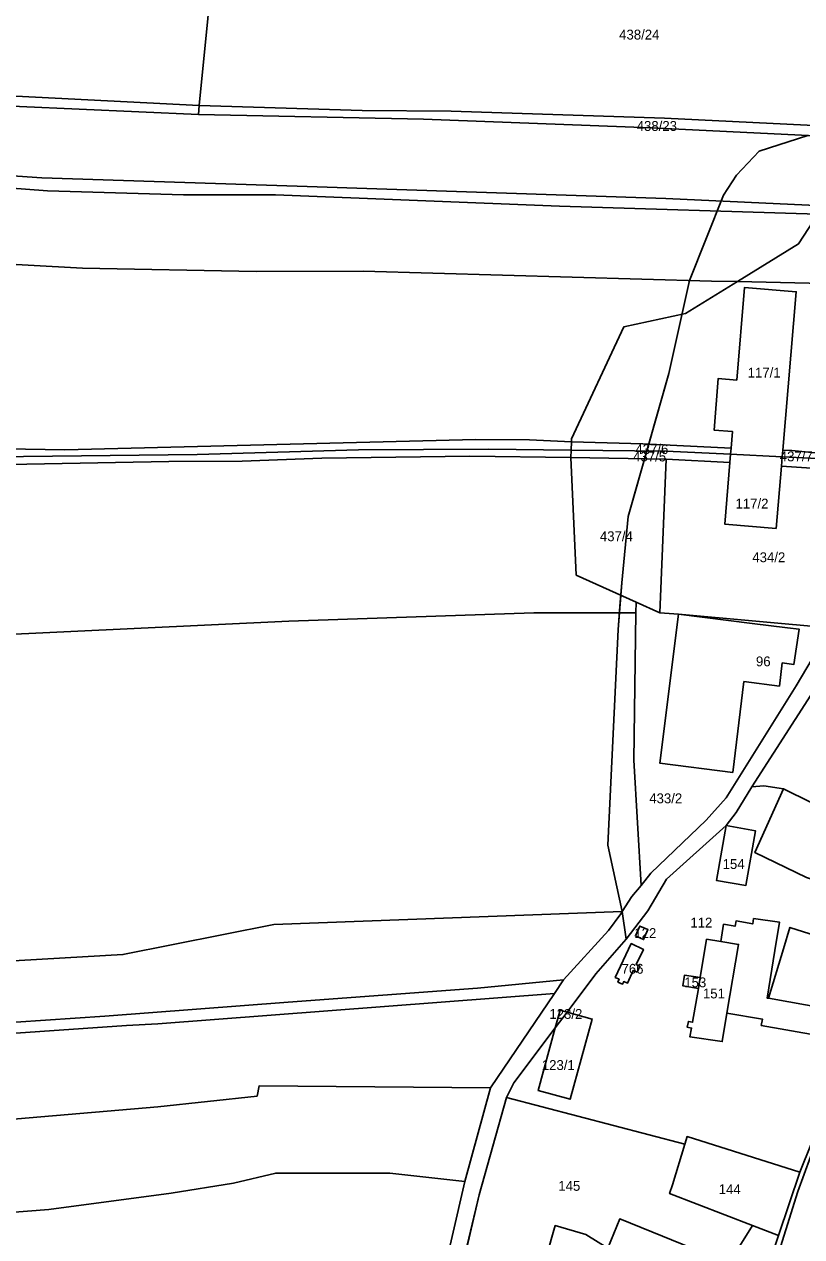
# Model space of a CAD drawing. Extents: x -629983 to -626385, y -1072828 to -1067897.
# Drawn here: x -627910.7 to -627674, y -1070665.2 to -1070295.9 of the extents above; entities that cross this region are included whole.
import ezdxf

# ---------------------------------------------------------------- set-up
doc = ezdxf.new("R2010")
doc.units = 0
for name, color, linetype in [('Parcela nároku', 7, 'Continuous'), ('Parcelní číslo', 7, 'Continuous'), ('Plocha PÚ', 7, 'Continuous'), ('Vnitřní obvod_šetřený', 7, 'Continuous')]:
    doc.layers.add(name, color=color, linetype=linetype)

msp = doc.modelspace()

# ---------------------------------------------------------------- linework, layer by layer
at = {"layer": 'Parcela nároku'}
for points in [[(-628060.11, -1070271.11), (-628056.15, -1070244.07), (-628008.92, -1070250.2), (-627943.87, -1070258.43), (-627852.12, -1070267.55), (-627857.41, -1070320.6), (-627935.31, -1070316.64), (-627972.58, -1070313.71), (-628063.81, -1070300.51)], [(-627694, -1070279.01), (-627762.73, -1070274.69), (-627852.12, -1070267.55), (-627857.41, -1070320.6), (-627807.86, -1070322.13), (-627780.69, -1070322.36), (-627715.75, -1070324.53), (-627668.16, -1070326.84), (-627643.99, -1070328.38), (-627633.37, -1070319.16), (-627623.56, -1070329.68), (-627607.68, -1070330.66), (-627612.15, -1070314.31), (-627620.1, -1070282.88)], [(-627975.41, -1070316.56), (-628013.39, -1070311.63), (-628064.17, -1070304.46), (-628158.28, -1070288.4), (-628169.7, -1070285.94), (-628193.03, -1070281.15), (-628197.85, -1070304.82), (-628163.72, -1070310.89), (-628107.67, -1070319.94), (-627998.49, -1070336.29), (-627905.29, -1070342.7), (-627827.64, -1070345.16), (-627715.35, -1070349), (-627667.5, -1070351.19), (-627663.96, -1070345.7), (-627647.13, -1070331.03), (-627719.77, -1070327.49), (-627789.19, -1070324.83), (-627857.63, -1070323.4), (-627930.45, -1070320.12)], [(-627935.31, -1070316.64), (-627857.41, -1070320.6), (-627857.63, -1070323.4), (-627930.45, -1070320.12), (-627975.41, -1070316.56), (-628013.39, -1070311.63), (-628064.17, -1070304.46), (-628063.81, -1070300.51), (-627972.58, -1070313.71)], [(-627903.57, -1070346.68), (-627931.89, -1070344.45), (-627993.13, -1070340.27), (-628115.46, -1070322.29), (-628198.34, -1070307.23), (-628203.34, -1070331.74), (-628177.12, -1070337.23), (-628130.58, -1070346.23), (-628080.75, -1070353.83), (-628037.7, -1070359.47), (-627955.53, -1070366.72), (-627892.97, -1070370.2), (-627840.14, -1070371.16), (-627807.49, -1070371.09), (-627701.48, -1070374.12), (-627693.61, -1070374.29), (-627674.98, -1070362.82), (-627669.14, -1070353.74), (-627747.72, -1070351.32), (-627834.23, -1070347.87), (-627862.19, -1070347.87)], [(-627998.49, -1070336.29), (-627905.29, -1070342.7), (-627827.64, -1070345.16), (-627715.35, -1070349), (-627667.5, -1070351.19), (-627669.14, -1070353.74), (-627747.72, -1070351.32), (-627834.23, -1070347.87), (-627862.19, -1070347.87), (-627903.57, -1070346.68), (-627931.89, -1070344.45), (-627993.13, -1070340.27), (-628115.46, -1070322.29), (-628198.34, -1070307.23), (-628197.85, -1070304.82), (-628163.72, -1070310.89), (-628107.67, -1070319.94)], [(-627668.16, -1070326.84), (-627643.99, -1070328.38), (-627647.13, -1070331.03), (-627719.77, -1070327.49), (-627789.19, -1070324.83), (-627857.63, -1070323.4), (-627857.41, -1070320.6), (-627807.86, -1070322.13), (-627780.69, -1070322.36), (-627715.75, -1070324.53)], [(-628177.12, -1070337.23), (-628130.58, -1070346.23), (-628080.75, -1070353.83), (-628037.7, -1070359.47), (-627955.53, -1070366.72), (-627892.97, -1070370.2), (-627840.14, -1070371.16), (-627807.49, -1070371.09), (-627701.48, -1070374.12), (-627693.61, -1070374.29), (-627709.42, -1070384.02), (-627728.14, -1070388.04), (-627744.07, -1070422.21), (-627744.1, -1070423.1), (-627756.84, -1070422.46), (-627773.24, -1070422.4), (-627898.31, -1070425.56), (-627958.23, -1070424.48), (-628036.03, -1070417.71), (-628090.14, -1070409.45), (-628153.81, -1070401.82), (-628201.61, -1070394.13), (-628215.5, -1070391.4), (-628203.34, -1070331.74)], [(-627693.61, -1070374.29), (-627674.98, -1070362.82), (-627669.14, -1070353.74), (-627648.82, -1070354.37), (-627643.94, -1070354.51), (-627645.62, -1070375.32)], [(-627695.51, -1070425.04), (-627695.66, -1070426.89), (-627679.96, -1070427.62), (-627679.79, -1070425.58), (-627675.69, -1070377.35), (-627691.41, -1070376.06), (-627693.77, -1070404.26), (-627699.4, -1070403.79), (-627700.71, -1070419.49), (-627695.08, -1070419.96)], [(-627958.23, -1070424.48), (-627898.31, -1070425.56), (-627773.24, -1070422.4), (-627756.84, -1070422.46), (-627744.1, -1070423.1), (-627744.2, -1070425.6), (-627769.34, -1070425.27), (-627808.9, -1070425.55), (-627858.09, -1070426.97), (-627919.9, -1070427.62), (-627966.92, -1070426.19), (-628033.7, -1070420.29), (-628089.12, -1070412.47), (-628156.9, -1070404.07), (-628181.33, -1070399.89), (-628215.91, -1070393.41), (-628215.5, -1070391.4), (-628201.61, -1070394.13), (-628153.81, -1070401.82), (-628090.14, -1070409.45), (-628036.03, -1070417.71)], [(-627919.9, -1070427.62), (-627858.09, -1070426.97), (-627808.9, -1070425.55), (-627769.34, -1070425.27), (-627744.2, -1070425.6), (-627744.29, -1070427.85), (-627775, -1070427.43), (-627820.12, -1070428.07), (-627844.34, -1070429.01), (-627866.68, -1070429.07), (-627926.22, -1070430.23), (-627965.43, -1070428.42), (-628014.16, -1070424.89), (-628033.19, -1070422.86), (-628064.04, -1070419.12), (-628138.5, -1070409.17), (-628183.83, -1070401.66), (-628216.36, -1070395.63), (-628215.91, -1070393.41), (-628181.33, -1070399.89), (-628156.9, -1070404.07), (-628089.12, -1070412.47), (-628033.7, -1070420.29), (-627966.92, -1070426.19)], [(-627744.2, -1070425.6), (-627744.1, -1070423.1), (-627722.35, -1070423.66), (-627695.51, -1070425.04), (-627695.66, -1070426.89), (-627715.31, -1070425.97)], [(-627744.29, -1070427.85), (-627744.2, -1070425.6), (-627715.31, -1070425.97), (-627695.66, -1070426.89), (-627695.87, -1070429.41), (-627715.32, -1070428.36)], [(-627744.29, -1070427.85), (-627715.32, -1070428.36), (-627717.24, -1070475.16), (-627724.44, -1070471.9), (-627742.66, -1070463.67)], [(-627647.27, -1070442.94), (-627647.6, -1070442), (-627646.48, -1070441.6), (-627646.58, -1070434.36), (-627668.03, -1070431.32), (-627680.2, -1070430.46), (-627681.82, -1070449.47), (-627697.43, -1070448.14), (-627695.87, -1070429.41), (-627715.32, -1070428.36), (-627717.24, -1070475.16), (-627711.57, -1070475.61), (-627664.39, -1070479.79), (-627651.75, -1070462.96), (-627646.33, -1070454.56), (-627646.47, -1070449.01), (-627646.98, -1070449.19), (-627648.99, -1070443.55)], [(-627695.66, -1070426.89), (-627695.87, -1070429.41), (-627697.43, -1070448.14), (-627681.82, -1070449.47), (-627680.2, -1070430.46), (-627679.96, -1070427.62)], [(-627669.22, -1070428.12), (-627654.23, -1070429.31), (-627642.29, -1070430.98), (-627635.77, -1070436.5), (-627640.32, -1070444.28), (-627641.98, -1070440), (-627646.48, -1070441.6), (-627646.58, -1070434.36), (-627668.03, -1070431.32), (-627680.2, -1070430.46), (-627679.96, -1070427.62)], [(-627666.89, -1070426.71), (-627654.23, -1070429.31), (-627669.22, -1070428.12), (-627679.96, -1070427.62), (-627679.79, -1070425.58), (-627676.98, -1070425.76)], [(-627711.57, -1070475.61), (-627664.39, -1070479.79), (-627670.84, -1070489.21), (-627675.73, -1070497.41), (-627697.01, -1070531.53), (-627703.09, -1070538.35), (-627719.93, -1070554.48), (-627722.93, -1070558.18), (-627725.07, -1070520.03), (-627724.49, -1070475.16), (-627724.44, -1070471.9), (-627717.24, -1070475.16)], [(-627689.14, -1070478.39), (-627678.33, -1070479.73), (-627674.75, -1070480.18), (-627676.37, -1070490.86), (-627679.94, -1070490.41), (-627680.82, -1070497.46), (-627691.59, -1070496.12), (-627695.02, -1070523.76), (-627717.2, -1070521.01), (-627711.57, -1070475.61)], [(-627695.02, -1070523.76), (-627691.59, -1070496.12), (-627680.82, -1070497.46), (-627679.94, -1070490.41), (-627676.37, -1070490.86), (-627674.75, -1070480.18), (-627678.33, -1070479.73), (-627689.14, -1070478.39), (-627711.57, -1070475.61), (-627717.2, -1070521.01)], [(-627679.55, -1070528.79), (-627688.24, -1070548.18), (-627672.57, -1070555.81), (-627659.9, -1070559.99), (-627657.81, -1070553.92), (-627656.38, -1070554.41), (-627654.85, -1070549.86), (-627646.49, -1070552.75), (-627648.05, -1070557.27), (-627645.57, -1070558.14), (-627636.82, -1070561.16), (-627634.81, -1070557.07), (-627632.41, -1070552.2), (-627631.8, -1070550.95), (-627629.3, -1070544.38), (-627643.07, -1070539.03), (-627661.2, -1070531.98), (-627662.07, -1070534.21), (-627668.95, -1070530.68), (-627671.18, -1070532.92)], [(-627697.05, -1070539.93), (-627688.09, -1070541.52), (-627691.02, -1070558.2), (-627699.97, -1070556.68)], [(-627697.05, -1070539.93), (-627699.97, -1070556.68), (-627691.02, -1070558.2), (-627688.09, -1070541.52)], [(-627694.01, -1070569.01), (-627688.94, -1070569.9), (-627688.67, -1070568.31), (-627680.79, -1070569.36), (-627682.19, -1070577.99), (-627684.57, -1070592.5), (-627684.12, -1070592.58), (-627655.37, -1070597.68), (-627656.91, -1070606.05), (-627661.42, -1070612.95), (-627663.99, -1070611.33), (-627660.34, -1070605.48), (-627686.35, -1070600.86), (-627685.99, -1070598.91), (-627696.8, -1070597.09), (-627693.25, -1070576.16), (-627698.67, -1070575.26), (-627697.8, -1070570.04), (-627694.32, -1070570.65)], [(-627723.29, -1070570.56), (-627724.64, -1070573.6), (-627722.16, -1070574.72), (-627720.81, -1070571.64)], [(-627724.64, -1070573.6), (-627722.16, -1070574.72), (-627720.81, -1070571.64), (-627723.29, -1070570.56)], [(-627661.28, -1070576.19), (-627677.62, -1070571.01), (-627679.57, -1070577.47), (-627684.12, -1070592.58), (-627655.37, -1070597.68), (-627649.93, -1070588.69), (-627654.69, -1070588.03), (-627655.85, -1070587.31), (-627652.89, -1070578.85)], [(-627727.06, -1070588.01), (-627728.2, -1070587.47), (-627728.59, -1070588.28), (-627729.99, -1070587.64), (-627729.62, -1070586.79), (-627730.76, -1070586.21), (-627725.9, -1070575.9), (-627722.22, -1070577.67), (-627724.43, -1070582.25), (-627723.27, -1070582.8), (-627724.14, -1070584.63), (-627725.3, -1070584.11)], [(-627729.99, -1070587.64), (-627729.62, -1070586.79), (-627730.76, -1070586.21), (-627725.9, -1070575.9), (-627722.22, -1070577.67), (-627724.43, -1070582.25), (-627723.27, -1070582.8), (-627724.14, -1070584.63), (-627725.3, -1070584.11), (-627727.06, -1070588.01), (-627728.2, -1070587.47), (-627728.59, -1070588.28)], [(-627705.42, -1070589.64), (-627704.88, -1070586.27), (-627702.99, -1070574.57), (-627698.67, -1070575.26), (-627693.25, -1070576.16), (-627696.8, -1070597.09), (-627698.21, -1070605.76), (-627708.08, -1070604.3), (-627707.56, -1070601.63), (-627708.86, -1070601.41), (-627708.52, -1070599.63), (-627707.24, -1070599.86)], [(-628026.25, -1070603.41), (-627971, -1070603.08), (-627922.42, -1070600.5), (-627886.17, -1070598.06), (-627830.32, -1070593.77), (-627772.67, -1070589.48), (-627746.55, -1070586.97), (-627749.28, -1070591.09), (-627870.03, -1070600.31), (-627879.61, -1070600.88), (-627932.47, -1070604.52), (-627970.45, -1070606.06), (-628033.95, -1070606.87), (-628104.75, -1070603.7), (-628116.52, -1070602.55), (-628142.22, -1070601.28), (-628164.51, -1070598.79), (-628179.7, -1070597.46), (-628254.76, -1070587.27), (-628254.21, -1070584.31), (-628247.39, -1070585.51), (-628174.13, -1070594.4), (-628110.42, -1070600.1), (-628064.48, -1070602.87)], [(-627709.66, -1070585.51), (-627704.88, -1070586.27), (-627705.42, -1070589.64), (-627710.16, -1070588.8)], [(-627749.04, -1070601.58), (-627754.27, -1070620.67), (-627744.48, -1070623.35), (-627737.76, -1070598.9), (-627745.41, -1070596.77)], [(-627747.55, -1070596.17), (-627749.04, -1070601.58), (-627745.41, -1070596.77)], [(-627772.16, -1070652.46), (-627763.86, -1070622.81), (-627709.63, -1070637.02), (-627713.35, -1070649.42), (-627714.22, -1070652.04), (-627688.97, -1070661.79), (-627701.56, -1070682.02), (-627704.43, -1070680.74), (-627700.66, -1070671.43), (-627729.41, -1070659.79), (-627732.99, -1070668.64), (-627739.76, -1070664.48), (-627749.05, -1070661.81), (-627754.38, -1070680.37), (-627764.27, -1070677.26), (-627764.08, -1070670.78), (-627775.97, -1070668.61)], [(-627709.63, -1070637.02), (-627708.93, -1070634.68), (-627674.6, -1070645.58), (-627681.09, -1070664.8), (-627688.97, -1070661.79), (-627714.22, -1070652.04), (-627713.35, -1070649.42)], [(-627704.07, -1070689.26), (-627704.43, -1070680.74), (-627700.66, -1070671.43), (-627729.41, -1070659.79), (-627732.99, -1070668.64), (-627739.76, -1070664.48), (-627749.05, -1070661.81), (-627754.38, -1070680.37), (-627745.41, -1070683.18), (-627743.14, -1070683.88), (-627739.98, -1070684.3), (-627721.56, -1070688.68), (-627705.54, -1070693.57)], [(-627701.56, -1070682.02), (-627688.97, -1070661.79), (-627681.09, -1070664.8), (-627689.42, -1070689.81)]]:
    msp.add_lwpolyline(points, close=True, dxfattribs=at)
for points in [[(-627666.89, -1070426.71), (-627676.98, -1070425.76), (-627679.79, -1070425.58), (-627675.69, -1070377.35), (-627691.41, -1070376.06), (-627693.77, -1070404.26), (-627699.4, -1070403.79), (-627700.71, -1070419.49), (-627695.08, -1070419.96), (-627695.51, -1070425.04), (-627722.35, -1070423.66), (-627744.1, -1070423.1), (-627744.07, -1070422.21), (-627728.14, -1070388.04), (-627709.42, -1070384.02), (-627693.61, -1070374.29), (-627645.62, -1070375.32)], [(-627926.22, -1070430.23), (-627866.68, -1070429.07), (-627844.34, -1070429.01), (-627820.12, -1070428.07), (-627775, -1070427.43), (-627744.29, -1070427.85), (-627742.66, -1070463.67), (-627724.44, -1070471.9), (-627724.49, -1070475.16), (-627755.53, -1070475.17), (-627830.1, -1070477.74), (-627922.31, -1070482.11)], [(-627956.15, -1070583.61), (-627880.67, -1070579.28), (-627834.69, -1070570.07), (-627728.64, -1070566.16), (-627725.73, -1070561.62), (-627722.93, -1070558.18), (-627725.07, -1070520.03), (-627724.49, -1070475.16), (-627755.53, -1070475.17), (-627830.1, -1070477.74), (-627922.31, -1070482.11)], [(-627784.25, -1070681.85), (-627776.6, -1070648.4), (-627768.8, -1070619.84), (-627749.28, -1070591.09), (-627746.55, -1070586.97), (-627732.84, -1070571.92), (-627729.09, -1070566.86), (-627728.64, -1070566.16), (-627725.73, -1070561.62), (-627722.93, -1070558.18), (-627719.93, -1070554.48), (-627703.09, -1070538.35), (-627697.01, -1070531.53), (-627675.73, -1070497.41), (-627670.84, -1070489.21)], [(-627669.39, -1070497.42), (-627689.21, -1070528.16), (-627694, -1070535.96), (-627697.05, -1070539.93), (-627715.18, -1070556.29), (-627720.89, -1070565.91), (-627727.45, -1070574.55), (-627736.65, -1070585.16), (-627745.41, -1070596.77), (-627747.55, -1070596.17), (-627749.04, -1070601.58), (-627761.66, -1070618.29), (-627763.86, -1070622.81), (-627772.16, -1070652.46), (-627775.97, -1070668.61)], [(-627669.39, -1070497.42), (-627689.21, -1070528.16), (-627685.51, -1070527.83), (-627679.55, -1070528.79), (-627671.18, -1070532.92)], [(-627672.57, -1070555.81), (-627688.24, -1070548.18), (-627679.55, -1070528.79), (-627685.51, -1070527.83), (-627689.21, -1070528.16), (-627694, -1070535.96), (-627697.05, -1070539.93), (-627715.18, -1070556.29), (-627720.89, -1070565.91), (-627727.45, -1070574.55), (-627736.65, -1070585.16), (-627745.41, -1070596.77), (-627737.76, -1070598.9), (-627744.48, -1070623.35), (-627754.27, -1070620.67), (-627749.04, -1070601.58), (-627761.66, -1070618.29), (-627763.86, -1070622.81), (-627709.63, -1070637.02), (-627708.93, -1070634.68), (-627674.6, -1070645.58), (-627667.48, -1070627.92)], [(-627689.42, -1070689.81), (-627681.09, -1070664.8), (-627674.6, -1070645.58), (-627667.48, -1070627.92), (-627663.32, -1070621.69), (-627654.2, -1070606.83), (-627653.79, -1070606.16), (-627647.92, -1070597.59), (-627643.48, -1070589.58), (-627625.71, -1070562.74), (-627615.15, -1070546.88), (-627608.75, -1070538.3), (-627622.12, -1070558.08), (-627628.65, -1070568.14), (-627645.23, -1070593.66), (-627658.6, -1070614.18), (-627664.52, -1070624.66), (-627666.36, -1070628.21), (-627669.39, -1070635.62), (-627675.15, -1070651.38), (-627682.5, -1070674.74)], [(-627956.15, -1070583.61), (-627880.67, -1070579.28), (-627834.69, -1070570.07), (-627728.64, -1070566.16), (-627729.09, -1070566.86), (-627732.84, -1070571.92), (-627746.55, -1070586.97), (-627772.67, -1070589.48), (-627830.32, -1070593.77), (-627886.17, -1070598.06), (-627922.42, -1070600.5)], [(-627660.34, -1070605.48), (-627686.35, -1070600.86), (-627685.99, -1070598.91), (-627696.8, -1070597.09), (-627698.21, -1070605.76), (-627708.08, -1070604.3), (-627707.56, -1070601.63), (-627708.86, -1070601.41), (-627708.52, -1070599.63), (-627707.24, -1070599.86), (-627705.42, -1070589.64), (-627710.16, -1070588.8), (-627709.66, -1070585.51), (-627704.88, -1070586.27), (-627702.99, -1070574.57), (-627698.67, -1070575.26), (-627697.8, -1070570.04), (-627694.32, -1070570.65), (-627694.01, -1070569.01), (-627688.94, -1070569.9), (-627688.67, -1070568.31), (-627680.79, -1070569.36), (-627682.19, -1070577.99), (-627684.57, -1070592.5), (-627684.12, -1070592.58), (-627679.57, -1070577.47), (-627677.62, -1070571.01), (-627661.28, -1070576.19)], [(-627921.14, -1070630.03), (-627870.01, -1070625.59), (-627839.8, -1070622.34), (-627839.21, -1070619.27), (-627768.8, -1070619.84), (-627749.28, -1070591.09), (-627870.03, -1070600.31), (-627879.61, -1070600.88), (-627932.47, -1070604.52)], [(-627921.14, -1070630.03), (-627870.01, -1070625.59), (-627839.8, -1070622.34), (-627839.21, -1070619.27), (-627768.8, -1070619.84), (-627776.6, -1070648.4), (-627799.38, -1070645.81), (-627834.12, -1070645.83), (-627847.02, -1070648.85), (-627865.99, -1070651.96), (-627903.25, -1070656.94), (-627969.61, -1070662.08)], [(-627669.39, -1070635.62), (-627675.15, -1070651.38), (-627682.5, -1070674.74)], [(-627911.39, -1070694.75), (-627878.35, -1070689.15), (-627854.84, -1070684.51), (-627823.66, -1070681.44), (-627822.81, -1070673.96), (-627784.25, -1070681.85), (-627776.6, -1070648.4), (-627799.38, -1070645.81), (-627834.12, -1070645.83), (-627847.02, -1070648.85), (-627865.99, -1070651.96), (-627903.25, -1070656.94), (-627969.61, -1070662.08)]]:
    msp.add_lwpolyline(points, dxfattribs=at)
at = {"layer": 'Plocha PÚ'}
msp.add_lwpolyline([(-627779.57, -1070683.51), (-627772.16, -1070652.46), (-627763.86, -1070622.81), (-627761.66, -1070618.29), (-627749.04, -1070601.58), (-627747.55, -1070596.17), (-627745.41, -1070596.77), (-627736.65, -1070585.16), (-627727.45, -1070574.55), (-627728.64, -1070566.16), (-627733.05, -1070545.94), (-627729.9, -1070480.2), (-627728.79, -1070466.04), (-627726.85, -1070445.83), (-627714.42, -1070402.27), (-627708.2, -1070373.93), (-627697.78, -1070347.99), (-627693.9, -1070341.82), (-627687.01, -1070334.57), (-627672.18, -1070329.81)], dxfattribs=at)
at = {"layer": 'Vnitřní obvod_šetřený'}
for p, q in [((-627687.01, -1070334.57), (-627672.18, -1070329.81)), ((-627693.9, -1070341.82), (-627687.01, -1070334.57)), ((-627697.78, -1070347.99), (-627693.9, -1070341.82)), ((-627708.2, -1070373.93), (-627697.78, -1070347.99)), ((-627714.42, -1070402.27), (-627708.2, -1070373.93)), ((-627720.64, -1070424.05), (-627714.42, -1070402.27)), ((-627726.85, -1070445.83), (-627720.64, -1070424.05)), ((-627728.79, -1070466.04), (-627726.85, -1070445.83)), ((-627729.34, -1070473.12), (-627728.79, -1070466.04)), ((-627729.9, -1070480.2), (-627729.34, -1070473.12)), ((-627736.65, -1070585.16), (-627727.45, -1070574.55)), ((-627775.97, -1070668.61), (-627772.16, -1070652.46))]:
    msp.add_line(p, q, dxfattribs=at)
for points in [[(-627727.45, -1070574.55), (-627728.64, -1070566.16), (-627733.05, -1070545.94), (-627729.9, -1070480.2)], [(-627772.16, -1070652.46), (-627763.86, -1070622.81), (-627761.66, -1070618.29), (-627749.04, -1070601.58), (-627747.55, -1070596.17), (-627745.41, -1070596.77), (-627736.65, -1070585.16)]]:
    msp.add_lwpolyline(points, dxfattribs=at)

# ---------------------------------------------------------------- texts
at = {"layer": 'Parcelní číslo'}
for s, p in [('438/24', (-627729.59, -1070300.54)), ('438/23', (-627724.25, -1070328.37)), ('117/1', (-627690.47, -1070403.5)), ('437/6', (-627724.65, -1070426.82)), ('437/5', (-627725.34, -1070429.05)), ('437/7', (-627680.68, -1070429.02)), ('117/2', (-627694.17, -1070443.39)), ('437/4', (-627735.46, -1070453.34)), ('434/2', (-627689.05, -1070459.74)), ('96', (-627687.94, -1070491.46)), ('433/2', (-627720.42, -1070533.17)), ('154', (-627698.09, -1070553.18)), ('112', (-627707.91, -1070571.03)), ('122', (-627724.97, -1070574.22)), ('766', (-627728.87, -1070585.1)), ('153', (-627709.76, -1070589.23)), ('151', (-627704.09, -1070592.61)), ('123/2', (-627750.83, -1070598.84)), ('123/1', (-627753.13, -1070614.42)), ('145', (-627748.11, -1070651.22)), ('144', (-627699.25, -1070652.21))]:
    msp.add_text(s, height=3, dxfattribs=at).set_placement(p)

doc.saveas('drawing.dxf')
